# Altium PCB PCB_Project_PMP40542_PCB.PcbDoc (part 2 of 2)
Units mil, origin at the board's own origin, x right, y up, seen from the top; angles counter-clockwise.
Board outline 1181.1 x 1181.1 mil, 4 copper layers (Top Layer, Signal Layer 1, Signal Layer 2, Bottom Layer), stack 42.8 mil thick; 61 components, 38 nets, 268 pads, 149 vias.
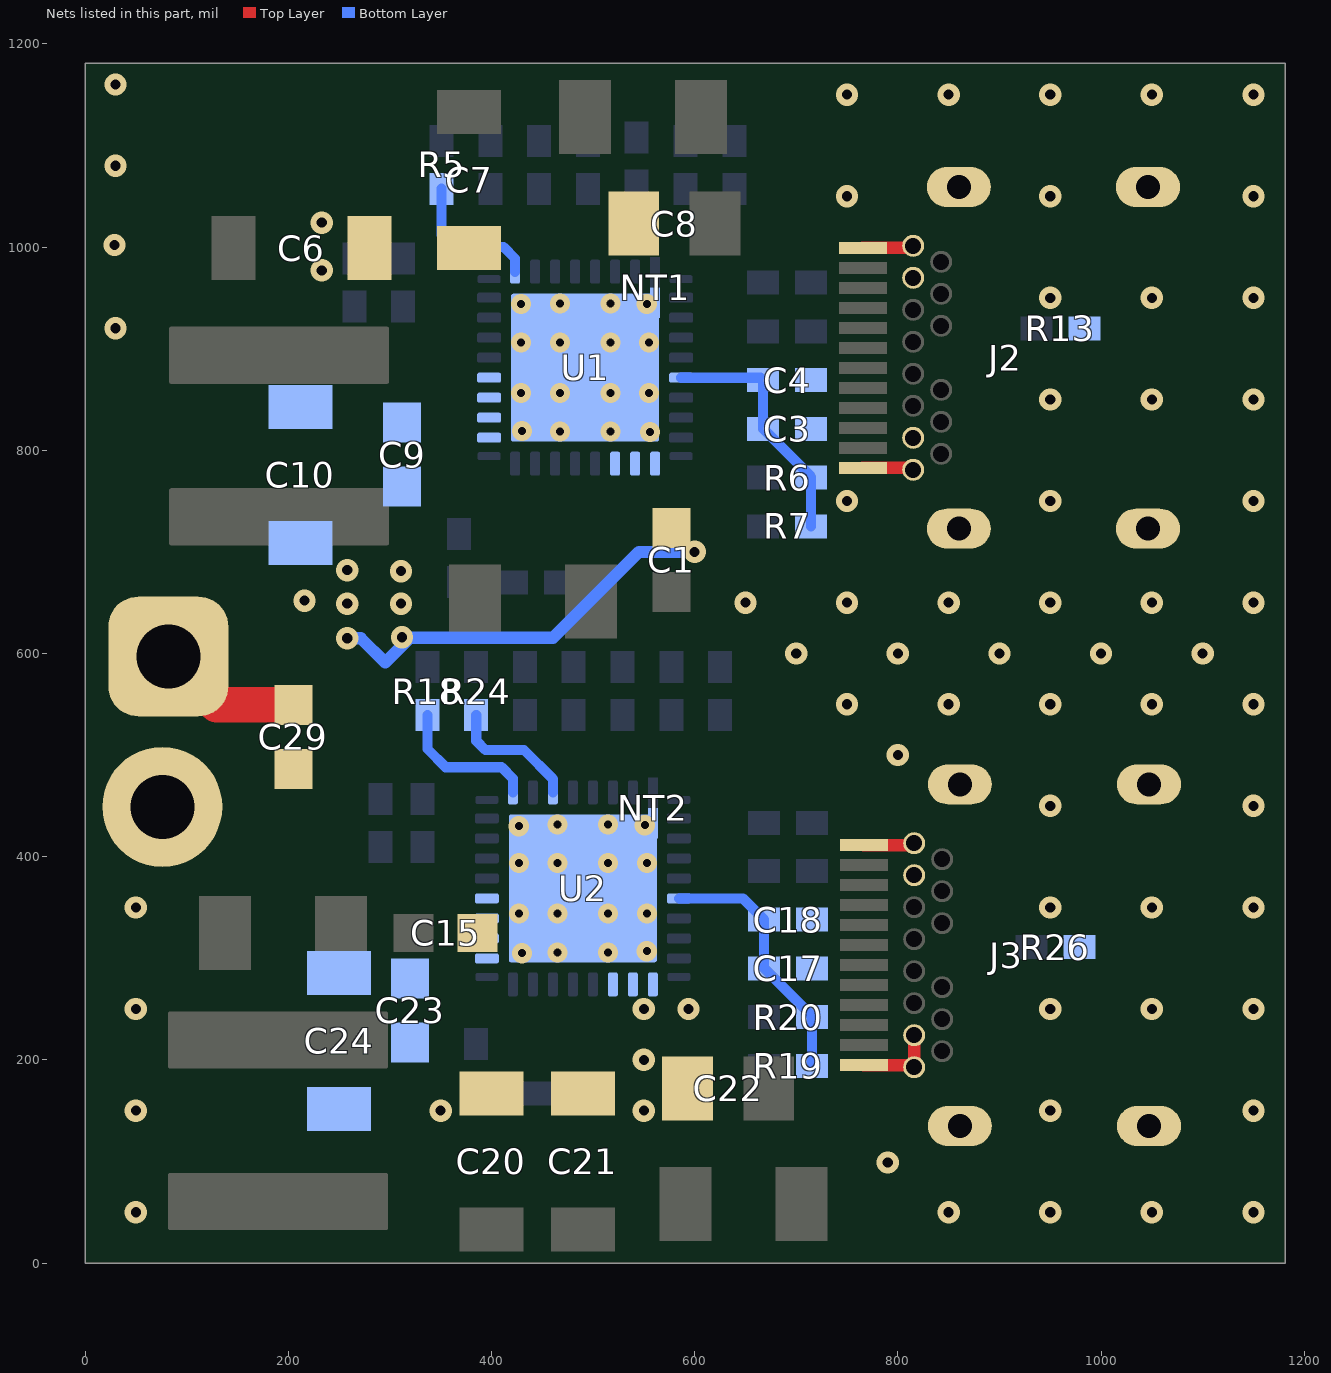
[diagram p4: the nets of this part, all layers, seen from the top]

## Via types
v1: diameter 22, hole 10, Top Layer to Bottom Layer, tented both sides, 72 vias
v2: diameter 10, hole 6, Top Layer to Bottom Layer, tented both sides, 31 vias
v3: diameter 19.68, hole 7.87, Top Layer to Bottom Layer, 24 vias
v4: diameter 30, hole 15, Top Layer to Bottom Layer, 14 vias
v5: diameter 20, hole 8, Top Layer to Bottom Layer, tented both sides, 8 vias

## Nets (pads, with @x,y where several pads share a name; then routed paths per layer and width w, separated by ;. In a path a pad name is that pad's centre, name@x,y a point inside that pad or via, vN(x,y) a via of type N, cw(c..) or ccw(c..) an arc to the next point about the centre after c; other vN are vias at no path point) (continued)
NetR24_2: R24.2 U2.11 | length 129.7
  Bottom Layer w10: R24.2@385,539.38 385,514 394,505 432,505 460.47,476.53 U2.11@460.47,463.23
PGND: C1.1 C3.2 C4.2 C6.2 C7.2 C8.2 C9.2 C10.2 C15.1 C17.2 C18.2 C20.2 C21.2 C22.2 C23.2 C24.2 C29.2 J2.A1 J2.A12 J2.B1 J2.B12 J2.M1 J2.M2 J2.S1 J2.S2 J2.S3 J2.S4 J3.A1 J3.A12 J3.B1 J3.B12 J3.M1 J3.M2 J3.S1 J3.S2 J3.S3 J3.S4 NT1.1 NT2.1 pad.2 R13.1 R26.1 U1.25 U1.26 U1.27 U1.33@492.16,881.25 U2.25 U2.26 U2.27 U2.33@490,368.74 | length 626.3
  Top Layer w12: J2.A1@765.46,782.73 813.1,782.73 J2.B12@815.07,780.76 ; J2.A12@765.46,999.27 813.1,999.27 J2.B1@815.07,1001.24 ; J3.A1@766.46,194.73 814.1,194.73 816.07,196.7 J3.M2@816.07,224.26 ; J3.A12@766.46,411.27 814.1,411.27 J3.B1@816.07,413.24
  Bottom Layer w12: v1(258,615) 271.43,615 295.43,591 319.8,615.37 460.55,615.37 545.18,700 v1(600,700)
  other v1: 50,50 850,50 950,50 1050,50 1150,50 790,99 50,150 350,150 550,150 950,150 1150,150 550,200 50,250 550,250 594,250 950,250 1050,250 1150,250 50,350 950,350 1050,350 1150,350 950,450 1150,450 800,500 750,550 850,550 950,550 1050,550 1150,550 700,600 800,600 900,600 1000,600 1100,600 312,616 258,649 311,649 650,650 750,650 850,650 950,650 1050,650 1150,650 216,652 311,681 258,682 750,750 950,750 1150,750 950,850 1050,850 1150,850 30,920 950,950 1050,950 1150,950 233,977 29,1002 233,1024 750,1050 950,1050 1150,1050 30,1080 750,1150 850,1150 950,1150 1050,1150 1150,1150 30,1160
  other v3: 465.2,305.75 514.8,305.75 427.01,343.94 465.2,343.94 514.8,343.94 552.99,343.94 427.01,393.54 465.2,393.54 514.8,393.54 552.99,393.54 465.2,431.73 514.8,431.73 467.35,818.26 516.96,818.26 429.17,856.45 467.35,856.45 516.96,856.45 555.15,856.45 429.17,906.06 467.35,906.06 516.96,906.06 555.15,906.06 467.35,944.24 516.96,944.24
  other v5: 430,305 553,307 427,430 551,431 556,818 430,819 429,944 553,944
RT_1: R5.2 U1.9 | length 140.3
  Bottom Layer w10: R5.2@351,1057.38 351,1012 363,1000 412,1000 423.26,988.74 U1.9@423.26,975.74
RT_2: R18.2 U2.9 | length 143.2
  Bottom Layer w10: R18.2@337,539.38 337,506 355,488 410,488 421.1,476.9 U2.9@421.1,463.23
VCC_1: C3.1 C4.1 R6.2 R7.2 U1.21 | length 245.3
  Bottom Layer w10: U1.21@586.65,871.41 664.97,871.41 C4.1@667.38,869 C3.1@667.38,821 714.62,773.76 R6.2@714.62,773 R7.2@714.62,725
VCC_2: C17.1 C18.1 R19.2 R20.2 U2.21 | length 256.1
  Bottom Layer w10: U2.21@584.49,358.9 647.48,358.9 C18.1@668.38,338 C17.1@668.38,290 715.62,242.76 R20.2@715.62,242 R19.2@715.62,194
VIN: C9.1 C10.1 C23.1 C24.1 C29.1 pad.1 U1.1 U1.2 U1.3 U1.4 U2.1 U2.2 U2.3 U2.4 | length 142.7
  Top Layer w35: pad.1@82,597 129.5,549.5 C29.1@205,549.5
pads on no net: J2.A2 J2.A3 J2.A8 J2.A10 J2.A11 J2.B2 J2.B3 J2.B8 J2.B10 J2.B11 J3.A2 J3.A3 J3.A8 J3.A10 J3.A11 J3.B2 J3.B3 J3.B8 J3.B10 J3.B11 U1.7 U1.10 U1.22 U1.23 U1.24 U1.33@442.55,831.65 U1.33@442.55,881.25 U1.33@442.55,930.86 U1.33@492.16,831.65 U1.33@492.16,881.25 U1.33@492.16,930.86 U1.33@541.76,831.65 U1.33@541.76,881.25 U1.33@541.76,930.86 U1.A1 U1.A2 U1.A3 U1.A4 U2.7 U2.10 U2.22 U2.23 U2.24 U2.33@440.39,319.13 U2.33@440.39,368.74 U2.33@440.39,418.35 U2.33@490,319.13 U2.33@490,368.74 U2.33@490,418.35 U2.33@539.61,319.13 U2.33@539.61,368.74 U2.33@539.61,418.35 U2.A1 U2.A2 U2.A3 U2.A4

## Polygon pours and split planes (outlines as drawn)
PGND on Bottom Layer "BOTTOM_LAYER_PGND_P030" (solid, remove dead copper, pour order 30): 20,1176 1172,1176 1179,1169 1179,12 1169,2 15,2 2,15 2,1158
VIN on Bottom Layer "BOTTOM_LAYER_VIN_P014" (solid, remove dead copper, pour order 14): 410,891 48,891 6,849 6,654 168,654 168,794 171,797 410,797
NetC5_2 on Bottom Layer "BOTTOM_LAYER_NETC5_2_P010" (solid, remove dead copper, pour order 10): 440,800 507,800 514,793 514,691 482,659 452,659 452,679 420,711 420,780
VIN on Bottom Layer "BOTTOM_LAYER_VIN_P002" (solid, remove dead copper, pour order 2): 407,366 410,363 410,296 407,293 380,293 369,282 369,259 365,255 217,255 163,309 163,500 131,532 28,532 6,554 6,664 168,664 270,562 270,389 293,366
NetC19_2 on Bottom Layer "BOTTOM_LAYER_NETC19_2_P000" (solid, remove dead copper, pour order 0): 435,285 505,285 510,280 510,250 515,245 515,160 510,155 475,155 470,160 470,190 465,195 430,195 420,205 420,240 430,250 430,280
PGND on Top Layer "TOP_LAYER_PGND_P024" (solid, remove dead copper, pour order 24): 20,1176 1172,1176 1179,1169 1179,12 1169,2 15,2 2,15 2,1158
NetC2_1 on Top Layer "TOP_LAYER_NETC2_1_P018" (solid, remove dead copper, pour order 18): 61,860 61,1093 144,1176 513,1176 523,1166 523,1089 485,1051 230,1051 210,1031 210,969 236,943 309,943 339,913 339,849 323,833 88,833
CSN_1 on Top Layer "TOP_LAYER_CSN_1_P016" (solid, remove dead copper, pour order 16): 583,1176 718,1176 731,1163 731,956 739,948 739,833 719,813 658,813 631,840 631,947 593,985 573,1005 573,1166
NetC5_2 on Top Layer "TOP_LAYER_NETC5_2_P012" (solid, remove dead copper, pour order 12): 80,819 391.02,819 412.02,798 498,798 510,786 510,710 498,698 80,698 70,708 70,809
CSN_2 on Top Layer "TOP_LAYER_CSN_2_P008" (solid, remove dead copper, pour order 8): 672,2 664,10 664,70 640,94 640,317 683,360 733,360 733,270 743,260 751,260 751,248 751,10 743,2
NetC16_1 on Top Layer "TOP_LAYER_NETC16_1_P006" (solid, remove dead copper, pour order 6): 615,120 623,112 623,10 615,2 84,2 70,16 70,110 80,120
NetC19_2 on Top Layer "TOP_LAYER_NETC19_2_P004" (solid, remove dead copper, pour order 4): 77,345 94.14,362.14 163.86,362.14 172,354 172,288 184,276 502,276 515,263 515,212 501,198 364,198 297,131 95,131 77,149
PGND on Signal Layer 2 "SIGNAL_LAYER_2_PGND_P028" (solid, remove dead copper, pour order 28): 20,1176 1172,1176 1179,1169 1179,12 1169,2 15,2 2,15 2,1158
NetC19_2 on Signal Layer 2 "SIGNAL_LAYER_2_NETC19_2_P022" (solid, remove dead copper, pour order 22): 85,276 502,276 515,263 515,204 493,182 253,182 212,141 85,141 77,149 77,268
NetC5_2 on Signal Layer 2 "SIGNAL_LAYER_2_NETC5_2_P020" (solid, remove dead copper, pour order 20): 498,798 412.02,798 391.02,819 155,819 145.98,809.98 145.98,708.02 156,698 498,698 510,710 510,786
PGND on Signal Layer 1 "SIGNAL_LAYER_1_PGND_P026" (solid, remove dead copper, pour order 26): 20,1176 1172,1176 1179,1169 1179,12 1169,2 15,2 2,15 2,1158

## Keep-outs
Keep-Out Layer:
  text ".Layer_Name" at 577,-858.49 h60

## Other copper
Top Layer:
  text ".Layer_Name" at 577,-858.49 h60
Signal Layer 1:
  pour cut-out: 802,431 802,336 803,335 796.29,328.29 783.71,328.29 698,414 698,431
Bottom Layer:
  text ".Layer_Name" at 577,-858.49 h60

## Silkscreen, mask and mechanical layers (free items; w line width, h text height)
Top Overlay:
  text "VIN" at 171,595 h50
  text "PMP40542" at 319,556 h50
  text "Rev.E1" at 320,515 h50
  text "GND" at 160,410 h50
  text ".Layer_Name" at 577,-858.49 h32
Bottom Overlay:
  lines w7: 798,136 803,126 803,163 ; 804,126 808,136
  text ".Layer_Name" at 577,-858.49 h32
Top Paste:
  text ".Layer_Name" at 577,-858.49 h60
Bottom Paste:
  text ".Layer_Name" at 577,-858.49 h60
Top Solder:
  text ".Layer_Name" at 577,-858.49 h60
  text ".Layer_Name" at 577,-858.49 h60
Bottom Solder:
  text ".Layer_Name" at 577,-858.49 h60
Drill Guide:
  text ".Layer_Name" at 577,-858.49 h60
M1 Board Outline:
  the board outline again, w10
  text ".Layer_Name" at 577,-858.49 h60
M2 Board Dimensions:
  rectangle: 125,-400 500,-275
  rectangle: 0,-275 125,-150
  lines w7: 0,-275 1000,-275 ; 125,-400 125,-150 ; 250,-400 250,-150 ; 500,-400 500,-150 ; 750,-400 750,-150 ; 0,-400 0,-150 1000,-150 1000,-400 0,-400
  text ".Layer_Name" at 577,-858.49 h60
M3 3D STEP Top:
  text ".Layer_Name" at 577,-858.49 h60
M4 3D STEP Bottom:
  text ".Layer_Name" at 577,-858.49 h60
M5 Assembly Top:
  lines w10: -292,-930.17 6308,-930.17 ; -292,-726.83 6310,-726.83 ; -292,-523.5 -292,-1133.5 3713,-1133.5 6310,-1133.5 6310,-523.5 -291.5,-523.5 -291.5,-1133.5 1284,-1133.5 ; 2173,-1133.5 2173,-523.5 ; 3440,-726.83 3440,-523.5 ; 4280,-726.83 4280,-523.5 ; 4902,-1140 4902,-937.17
  text "COMPONENTS MARKED 'DNP' SHOULD NOT BE POPULATED." at 1153.5,-318.5 h60
  text "ASSEMBLY VARIANT:" at 1153,-434 h60
  text ".VariantName" at 2189,-434 h60
  text "PCB VIEWED FROM TOP SIDE" at -228.5,-655.67 h60
  text "BOARD #:" at 2248,-655.67 h60
  text ".PRJ_Number" at 2793.5,-655.67 h60
  text "REV:" at 3638,-655.67 h60
  text ".PCB_Rev" at 3929.5,-655.67 h60
  text "SVN REV:" at 4476,-655.67 h60
  text ".VersionControl_RevNumber" at 4982,-655.67 h60
  text "TID #:" at 2248,-859 h60
  text ".TID" at 2793.5,-859 h60
  text "PLOT NAME =" at -228.5,-1064.34 h60
  text ".plot_File_Name" at 577,-1064.34 h60
  text "GENERATED    :" at 2250,-1064.34 h60
  text ".Print_Date" at 3119.5,-1064.34 h60
  text ".Print_Time" at 3848.5,-1064.34 h60
  text "TEXAS INSTRUMENTS" at 5113,-1064.34 h60
M6 Assembly Bottom:
  lines w10: -292.5,-727.33 6309.5,-727.33 ; -290.5,-930.67 6309.5,-930.67 ; 1115.5,-1140.5 1115.5,-937.67 ; 1737.5,-727.33 1737.5,-524 ; 2577.5,-727.33 2577.5,-524 ; 3844.5,-1134 3844.5,-524 ; 4733.5,-1134 6309,-1134 6309,-524 -292.5,-524 -292.5,-1134 2304.5,-1134 6309.5,-1134 6309.5,-524
  text "COMPONENTS MARKED 'DNP' SHOULD NOT BE POPULATED." at 6102,-318 h60
  text ".VariantName" at 5058,-434 h60
  text "ASSEMBLY VARIANT:" at 6097,-434 h60
  text ".VersionControl_RevNumber" at 1035.5,-656.17 h60
  text "SVN REV:" at 1541.5,-656.17 h60
  text ".PCB_Rev" at 2088,-656.17 h60
  text "REV:" at 2379.5,-656.17 h60
  text ".PRJ_Number" at 3224,-656.17 h60
  text "BOARD #:" at 3769.5,-656.17 h60
  text "PCB VIEWED FROM BOTTOM SIDE" at 6246,-656.17 h60
  text ".TID" at 3224,-859.5 h60
  text "TID #:" at 3769.5,-859.5 h60
  text "TEXAS INSTRUMENTS" at 904.5,-1064.84 h60
  text ".Print_Time" at 2169,-1064.84 h60
  text ".Print_Date" at 2898,-1064.84 h60
  text "GENERATED    :" at 3767.5,-1064.84 h60
  text ".plot_File_Name" at 5440.5,-1064.84 h60
  text "PLOT NAME =" at 6246,-1064.84 h60
M9 Title Sheet:
  drawing of 57 lines, arcs and shapes, not listed
  text "1" at 739.84,8036.5 h70
  text "2" at 3235.5,8036.5 h70
  text "3" at 5724.84,8036.5 h70
  text "4" at 8231.51,8036.5 h70
  text "5" at 10730.5,8036.5 h70
  text "6" at 13235.5,8036.5 h70
  text "A" at -416.5,6893.5 h70
  text "A" at 14383.5,6893.5 h70
  text "B" at -416.5,4513.5 h70
  text "B" at 14383.5,4513.5 h70
  text "C" at -416.5,2138.5 h70
  text "C" at 14383.5,2138.5 h70
  text "PROJECT TITLE:" at 11343.5,277.5 h45
  text ".PRJ_Title" at 11393.5,144.17 h70
  text "DESIGNED FOR:" at 11343.5,-23.5 h45
  text ".PRJ_Customer" at 11393.5,-163.5 h70
  text "D" at -416.5,-231.5 h70
  text "D" at 14383.5,-231.5 h70
  text "FILE NAME:" at 11343.5,-323.5 h45
  text ".PCB_File_Name_No_Path" at 11393.5,-443.5 h70
  text "Texas Instruments (TI) and/or its licensors do not warrant the accuracy or completeness of this specification" at 6374,-605.34 h45
  text "ENGINEER:" at 11343.5,-613.5 h45
  text "LAYOUT BY:" at 12848.5,-613.5 h45
  text "or any information contained therein. TI and/or its licensors do not warrant that this design will meet" at 6329.01,-718 h45
  text ".PRJ_Engineer" at 11393.5,-768.49 h70
  text ".PCB_Layout" at 12899,-768.49 h70
  text "the specifications, will be suitable for your application or fit for any particular purpose, or will operate in" at 6329.01,-830.67 h45
  text ".Layer_Name" at 577,-858.49 h60
  text "ALTIUM DESIGNER VERSION:" at 12848.5,-923.5 h45
  text "an implementation. TI and/or its licensors do not warrant that the design is production worthy. You should" at 6329.01,-943.33 h45
  text "completely validate and test your design implementation to confirm the system functionality for your application." at 6374,-1056 h45
  text ".print_Scale" at 11393.5,-1056.83 h70
  text ".Application_BuildNumber" at 12899,-1056.83 h70
  text "1" at 739.84,-1263.5 h70
  text "2" at 3235.5,-1263.5 h70
  text "3" at 5724.84,-1263.5 h70
  text "4" at 8231.51,-1263.5 h70
  text "5" at 10730.5,-1263.5 h70
  text "6" at 13235.5,-1263.5 h70
M10 Fab Notes:
  drawing of 189 lines, arcs and shapes, not listed
  text "DESIGN INFORMATION" at 12382.02,6356.17 h60
  text "MIN. TRACK WIDTH:" at 11737.46,6224.05 h60
  text "8" at 12833.7,6224.05 h60
  text "MIL" at 12988.46,6224.05 h60
  text "MIN. CLEARANCE:" at 11737.46,6099.92 h60
  text "0.2" at 12773.7,6099.93 h60
  text "mm" at 12988.46,6099.92 h60
  text "MIN. VIA PAD SIZE:" at 11737.46,5975.8 h60
  text "24" at 12803.71,5975.8 h60
  text "MIL" at 12988.46,5975.8 h60
  text "0.05mm (2MIL)" at 12432.46,5845.9 h60
  text "MINIMUM ANNULAR RING" at 11408.23,5837.67 h60
  text "EXTERNAL" at 13140.46,5837.67 h60
  text "PER" at 11608.23,5727.55 h60
  text "IPC-D-275 CLASS 2 LEVEL C" at 11828.23,5727.54 h60
  text "MIL, HOLES" at 13316.46,5627.07 h60
  text "+/-" at 12924,5618.48 h60
  text "+/-" at 13778,5618.48 h60
  text "REGISTRATION TOLERANCES:" at 11408.23,5617.42 h60
  text "METAL" at 12608,5617.42 h60
  text "5" at 13184.2,5617.42 h60
  text "3" at 14017.2,5617.42 h60
  text "MIL" at 14133.46,5617.42 h60
  text "HOLE SIZE TOLERANCE (UNLESS OTHERWISE SPECIFIED):" at 11408.23,5519.1 h60
  text "+/-" at 13778,5516.23 h60
  text "3" at 14017.2,5515.17 h60
  text "MIL" at 14133.46,5515.17 h60
  text "MATERIAL:" at 11333.46,5377.52 h60
  text "FR-4 High Tg" at 12319.9,5249 h60
  text "X" at 12175.46,5241.01 h60
  text "FR-408" at 11754.46,5236.49 h60
  text "OTHER" at 13242.46,5236.49 h60
  text "62 MIL (1.6mm) +/-10%" at 12074.56,5093.46 h60
  text "X" at 11954.46,5091.01 h60
  text "THICKNESS:" at 11408.23,5085.24 h60
  text "OTHER" at 13359.46,5085.24 h60
  text "TOLERANCE:" at 11408.23,4946.92 h60
  text "X" at 12256.46,4946.92 h60
  text "ANSI IPC-6012 TYPE 3 CLASS 2" at 12434.48,4946.92 h60
  text "OTHER +/-" at 12434.46,4802.73 h60
  text "BOW & TWIST:" at 11408.23,4657.54 h60
  text "X" at 12256.46,4657.54 h60
  text "ANSI IPC-6012 TYPE 3 CLASS 2" at 12434.48,4657.54 h60
  text "OTHER +/-" at 12434.46,4510.85 h60
  text "DRILLING:" at 11333.46,4380.23 h60
  text "NC_DRILL FILES" at 13094.46,4275.04 h60
  text "REFERENCE:" at 11408.23,4271.1 h60
  text "X" at 12065.46,4271.01 h60
  text "AS SHOWN" at 12243.46,4271.1 h60
  text "X" at 12966.46,4271.1 h60
  text "OTHER" at 13392.46,4128.85 h60
  text "PTH COPPER THICKNESS:" at 11407.91,4125.32 h60
  text "X" at 12547.14,4125.32 h60
  text "20-30 um" at 12675.14,4125.32 h60
  text "BOARD FINISH:" at 11333.46,3977.73 h60
  text "SILKSCREEN:" at 11488.68,3867.6 h60
  text "X" at 12446.46,3867.6 h60
  text "TOP" at 12563.46,3867.6 h60
  text "X" at 12956.46,3867.6 h60
  text "BOTTOM" at 13074.46,3867.6 h60
  text "SILKSCREEN COLOR:" at 11488.68,3712.41 h60
  text "X" at 12445.46,3712.41 h60
  text "WHITE" at 12563.46,3712.41 h60
  text "OTHER" at 13074.46,3712.41 h60
  text "X" at 12576.46,3568.96 h60
  text "GREEN" at 12694.46,3568.96 h60
  text "OTHER" at 13312.46,3568.96 h60
  text "SOLDER RESIST COLOR:" at 11488.68,3562.1 h60
  text "X" at 12576.46,3414.71 h60
  text "MATTE" at 12694.46,3414.71 h60
  text "SEMI-GLOSS" at 13312,3414.07 h60
  text "IMMERSION GOLD (ENIG)" at 12394.46,3241.94 h60
  text "ENEPIG" at 13732,3234.72 h60
  text "SURFACE FINISH:" at 11333.46,3233.72 h60
  text "X" at 12216.46,3233.72 h60
  text "IMM. TIN/SILVER OR EQUIV" at 11663,3096.4 h60
  text "OTHER" at 13094.46,3092.47 h60
  text "ARRAY/PANEL:" at 11333.46,2937.09 h60
  text "CUT AND TRIM PER M1 BOARD OUTLINE" at 12394.46,2928.87 h60
  text "N.C. ROUTE" at 12394.46,2792.9 h60
  text "X" at 13082.46,2792.9 h60
  text "V. SCORE" at 13260.46,2792.9 h60
  text "CERTIFICATION:" at 11333.46,2663.77 h60
  text "MATERIALS AND WORKMANSHIP FOR ALL PCBS" at 12058.46,2663.77 h60
  text "TO MEET OR EXCEED THE REQUIREMENTS OF:" at 12058.46,2569.71 h60
  text "X" at 11695.97,2441.08 h60
  text "ANSI IPC-A-600F CLASS ->" at 11823.96,2441.08 h60
  text "X" at 13471.97,2441.08 h60
  text "2" at 13581.96,2441.08 h60
  text "1" at 13266.96,2439.58 h60
  text "3" at 13935.96,2439.58 h60
  text "X" at 12507.97,2293.39 h60
  text "RoHS" at 12635.96,2293.39 h60
  text "OTHER" at 13280.36,2293.39 h60
  text "PER ORDER" at 13677.42,2293.39 h60
  text "ALL BOARDS MUST MEET OR EXCEED UL94-V0 REQUIREMENTS." at 11361,2139.57 h60
  text "PCB MUST BEAR THE UL94V-0 UL REGISTERED MATERIAL ID NUMBER" at 11361,2023.5 h60
  text "ADDITIONAL REQUIREMENTS:" at 11333.46,1854.08 h60
  text "MICROSECTION:" at 11408.23,1746.95 h60
  text "YES" at 12313.96,1746.95 h60
  text "REQUIRED" at 13175.46,1602.62 h60
  text "BARE BOARD ELEC. TEST:" at 11408.23,1599.76 h60
  text "NONE" at 12713.96,1599.76 h60
  text "X" at 13057.46,1599.76 h60
  text "PER ORDER" at 13767.46,1599.76 h60
  text "XX MIL VIAS REQUIRE NON-CONDUCTIVE FILL AND PLANARIZE" at 11576.38,1394.82 h59
  text "XX MIL VIAS REQUIRE CONDUCTIVE FILL AND PLANARIZE" at 11584.38,1290.84 h60
  text "OUTER XX MIL TRACES REQUIRE 50 OHM SINGLE-ENDED IMPEDANCE" at 11583.39,1127.46 h58
  text "LAYER 2 & 3 (INNER LAYERS) XX MIL WIDE, XX MIL SPACE / TRACES REQUIRE 100 OHM DIFFERENTIAL IMPEDANCE" at 11575.39,891.74 h60
  text ".Layer_Name" at 577,-858.49 h60
M11 Gerber Information:
  lines w10: -292,-930.17 6308,-930.17 ; -292,-726.83 6310,-726.83 ; -292,-523.5 -292,-1133.5 3713,-1133.5 6310,-1133.5 6310,-523.5 -291.5,-523.5 -291.5,-1133.5 1284,-1133.5 ; 2173,-1133.5 2173,-523.5 ; 3440,-726.83 3440,-523.5 ; 4280,-726.83 4280,-523.5 ; 4902,-1140 4902,-937.17
  text "ALL ARTWORK VIEWED FROM TOP SIDE" at -228.5,-655.67 h60
  text "BOARD #:" at 2248,-655.67 h60
  text ".PRJ_Number" at 2793.5,-655.67 h60
  text "REV:" at 3638,-655.67 h60
  text ".PCB_Rev" at 3929.5,-655.67 h60
  text "SVN REV:" at 4476,-655.67 h60
  text ".VersionControl_RevNumber" at 4982,-655.67 h60
  text "LAYER NAME =" at -228.5,-858.49 h60
  text "TID #:" at 2248,-859 h60
  text ".TID" at 2793.5,-859 h60
  text "PLOT NAME =" at -228.5,-1064.34 h60
  text ".plot_File_Name" at 577,-1064.34 h60
  text "GENERATED    :" at 2250,-1064.34 h60
  text ".Print_Date" at 3119.5,-1064.34 h60
  text ".Print_Time" at 3848.5,-1064.34 h60
  text "TEXAS INSTRUMENTS" at 5113,-1064.34 h60
M12 Stackup:
  drawing of 295 lines, arcs and shapes, not listed
  text "Layer" at 9797.84,7830 h60
  text "Name" at 10207.76,7830 h60
  text "Material" at 11147.5,7830 h60
  text "Thickness" at 12007.26,7830 h60
  text "Constant" at 12657.1,7830 h60
  text "Board Layer Stack" at 13226.96,7830 h60
  text "1" at 9797.84,7710 h60
  text "Top Overlay" at 10207.76,7710 h60
  text "2" at 9797.84,7590 h60
  text "Top Solder" at 10207.76,7590 h60
  text "Solder Resist" at 11147.5,7590 h60
  text "0.40mil" at 12007.26,7590 h60
  text "3.5" at 12657.1,7590 h60
  text "3" at 9797.84,7470 h60
  text "Top Layer" at 10207.76,7470 h60
  text "Copper" at 11147.5,7470 h60
  text "2.80mil" at 12007.26,7470 h60
  text "4" at 9797.84,7350 h60
  text "Dielectric 1" at 10207.76,7350 h60
  text "FR-4" at 11147.5,7350 h60
  text "5.00mil" at 12007.26,7350 h60
  text "4.2" at 12657.1,7350 h60
  text "5" at 9797.84,7230 h60
  text "Signal Layer 1" at 10207.76,7230 h60
  text "Copper" at 11147.5,7230 h60
  text "1.40mil" at 12007.26,7230 h60
  text "6" at 9797.84,7110 h60
  text "Dielectric 2" at 10207.76,7110 h60
  text "FR-4" at 11147.5,7110 h60
  text "24.40mil" at 12007.26,7110 h60
  text "4.2" at 12657.1,7110 h60
  text "7" at 9797.84,6990 h60
  text "Signal Layer 2" at 10207.76,6990 h60
  text "Copper" at 11147.5,6990 h60
  text "1.40mil" at 12007.26,6990 h60
  text "8" at 9797.84,6870 h60
  text "Dielectric 3" at 10207.76,6870 h60
  text "FR-4" at 11147.5,6870 h60
  text "5.00mil" at 12007.26,6870 h60
  text "4.2" at 12657.1,6870 h60
  text "9" at 9797.84,6750 h60
  text "Bottom Layer" at 10207.76,6750 h60
  text "Copper" at 11147.5,6750 h60
  text "2.80mil" at 12007.26,6750 h60
  text "10" at 9797.84,6630 h60
  text "Bottom Solder" at 10207.76,6630 h60
  text "Solder Resist" at 11147.5,6630 h60
  text "0.40mil" at 12007.26,6630 h60
  text "3.5" at 12657.1,6630 h60
  text "11" at 9797.84,6510 h60
  text "Bottom Overlay" at 10207.76,6510 h60
  text ".Layer_Name" at 577,-858.49 h60
M13 Component Bodies Top:
  text ".Layer_Name" at 577,-858.49 h60
M14 Component Bodies Bottom:
  text ".Layer_Name" at 577,-858.49 h60
M15 Courtyards Top:
  text ".Layer_Name" at 577,-858.49 h60
M16 Courtyards Bottom:
  text ".Layer_Name" at 577,-858.49 h60
Drill Drawing:
  circle w10: c5348.9,2610.75 r22.14
  lines w10: 5326.76,2688.23 5371.04,2688.23 5371.04,2732.51 5326.76,2732.51 5326.76,2688.23 ; 5326.76,2832.13 5371.04,2832.13 5348.9,2787.85 5326.76,2832.13 ; 5326.76,2898.54 5337.83,2898.54 5337.83,2887.47 5359.97,2887.47 5359.97,2898.54 5371.04,2898.54 5371.04,2920.68 5359.97,2920.68 5359.97,2931.75 5337.83,2931.75 5337.83,2920.68 5326.76,2920.68 5326.76,2898.54 ; 5326.76,2987.1 5348.9,2998.17 5371.04,2987.1 5359.97,3009.23 5371.04,3031.37 5348.9,3020.3 5326.76,3031.37 5337.83,3009.23 5326.76,2987.1 ; 5326.76,3086.72 5326.76,3097.79 5337.83,3108.86 5326.76,3119.93 5326.76,3131 5337.83,3131 5348.9,3119.93 5359.97,3131 5371.04,3131 5371.04,3119.93 5359.97,3108.86 5371.04,3097.79 5371.04,3086.72 5359.97,3086.72 5348.9,3097.79 5337.83,3086.72 5326.76,3086.72 ; 5326.76,3197.41 5337.83,3197.41 5348.9,3186.34 5359.97,3197.41 5371.04,3197.41 5359.97,3208.48 5371.04,3219.55 5359.97,3219.55 5348.9,3230.62 5337.83,3219.55 5326.76,3219.55 5337.83,3208.48 5326.76,3197.41 ; 5326.76,3308.1 5348.9,3285.96 5371.04,3308.1 5348.9,3330.24 5326.76,3308.1
  lines w12: 5286,2558.72 8398.94,2558.72 ; 5286,3355.7 8398.94,3355.7 ; 5601.63,2459.1 5601.63,3455.32 ; 5918.82,2459.1 5918.82,3455.32 ; 6540.56,2459.1 6540.56,3455.32 ; 6784.88,2459.1 6784.88,3455.32 ; 7145.22,2459.1 7145.22,3455.32 ; 7854.73,2459.1 7854.73,3455.32 ; 5286,2459.1 8398.94,2459.1 8398.94,3455.32 5286,3455.32 5286,2459.1
  text "Symbol" at 5345.77,3385.59 h72
  text "Quantity" at 5631.52,3385.59 h72
  text "Finished Hole Size" at 5948.7,3385.59 h72
  text "Plated" at 6570.45,3385.59 h72
  text "Hole Type" at 6814.77,3385.59 h72
  text "Drill Layer Pair" at 7175.11,3385.59 h72
  text "Hole Tolerance" at 7884.62,3385.59 h72
  text "31" at 5631.52,3285.96 h60
  text "6.00mil (0.152mm)" at 5948.7,3285.96 h60
  text "PTH" at 6570.45,3285.96 h60
  text "Round" at 6814.77,3285.96 h60
  text "Top Layer - Bottom Layer" at 7175.11,3285.96 h60
  text "24" at 5631.52,3186.34 h60
  text "7.87mil (0.200mm)" at 5948.7,3186.34 h60
  text "PTH" at 6570.45,3186.34 h60
  text "Round" at 6814.77,3186.34 h60
  text "Top Layer - Bottom Layer" at 7175.11,3186.34 h60
  text "8" at 5631.52,3086.72 h60
  text "8.00mil (0.203mm)" at 5948.7,3086.72 h60
  text "PTH" at 6570.45,3086.72 h60
  text "Round" at 6814.77,3086.72 h60
  text "Top Layer - Bottom Layer" at 7175.11,3086.72 h60
  text "72" at 5631.52,2987.1 h60
  text "10.00mil (0.254mm)" at 5948.7,2987.1 h60
  text "PTH" at 6570.45,2987.1 h60
  text "Round" at 6814.77,2987.1 h60
  text "Top Layer - Bottom Layer" at 7175.11,2987.1 h60
  text "14" at 5631.52,2887.47 h60
  text "15.00mil (0.381mm)" at 5948.7,2887.47 h60
  text "PTH" at 6570.45,2887.47 h60
  text "Round" at 6814.77,2887.47 h60
  text "Top Layer - Bottom Layer" at 7175.11,2887.47 h60
  text "28" at 5631.52,2787.85 h60
  text "15.75mil (0.400mm)" at 5948.7,2787.85 h60
  text "PTH" at 6570.45,2787.85 h60
  text "Round" at 6814.77,2787.85 h60
  text "Top Layer - Bottom Layer" at 7175.11,2787.85 h60
  text "2" at 5631.52,2688.23 h60
  text "62.99mil (1.600mm)" at 5948.7,2688.23 h60
  text "PTH" at 6570.45,2688.23 h60
  text "Round" at 6814.77,2688.23 h60
  text "Top Layer - Bottom Layer" at 7175.11,2688.23 h60
  text "8" at 5631.52,2588.61 h60
  text "23.62mil (0.600mm)" at 5948.7,2588.61 h60
  text "PTH" at 6570.45,2588.61 h60
  text "Slot" at 6814.77,2588.61 h60
  text "Top Layer - Bottom Layer" at 7175.11,2588.61 h60
  text "187 Total" at 5631.52,2488.98 h60
  text "Slot definitions :" at 5345.77,2409.37 h60
  text "Routed Path Length" at 5789.08,2409.37 h60
  text "= Calculated from tool start centre position to tool end centre position." at 6321.41,2409.37 h60
  text "Hole Length" at 5789.08,2359.64 h60
  text "= Routed Path Length + Tool Size = Slot length as defined in the PCB layout" at 6121.61,2359.64 h60
  text ".Layer_Name" at 577,-858.49 h60
Mechanical 17:
  text ".Layer_Name" at 577,-858.49 h60
Mechanical 18:
  text ".Layer_Name" at 577,-858.49 h60
Mechanical 19:
  text ".Layer_Name" at 577,-858.49 h60

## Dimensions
0,0 to 1181.1,0 on M2 Board Dimensions
0,0 to 0,1181.1 on M2 Board Dimensions
0,-400 to 1000,-400 on M2 Board Dimensions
